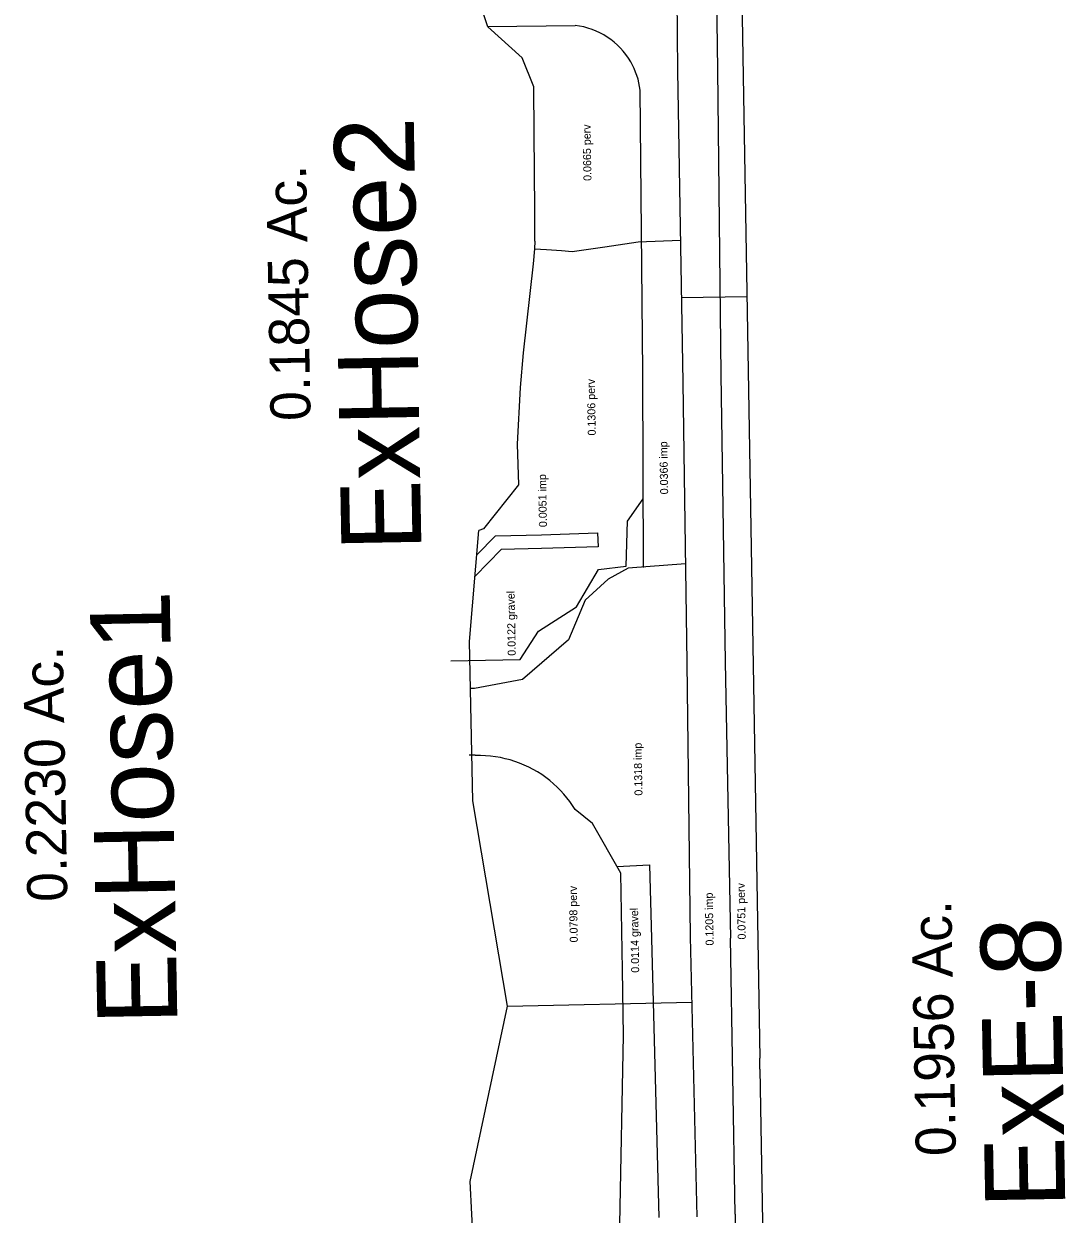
# Model space of a CAD drawing. Extents: x 925564 to 926134, y 853260 to 858402.
# Drawn here: x 925563.8 to 925928.2, y 855967.9 to 856384.4 of the extents above; entities that cross this region are included whole.
import ezdxf

# ---------------------------------------------------------------- set-up
doc = ezdxf.new("R2010")
doc.units = 0
for name, color, linetype in [('DrainDivides01', 7, 'Continuous'), ('PavtMisc_ep', 7, 'Continuous'), ('TextLabel', 7, 'Continuous')]:
    doc.layers.add(name, color=color, linetype=linetype)

msp = doc.modelspace()

# ---------------------------------------------------------------- linework, layer by layer
at = {"layer": 'DrainDivides01'}
for p, q in [((925810.15, 856680.63), (925821.34, 856022.48)), ((925792.29, 856393.71), (925792.52, 856367.9)), ((925792.52, 856367.9), (925794.36, 856258.9)), ((925778.8, 856308.05), (925793.52, 856308.63)), ((925793.86, 856288.6), (925816.81, 856288.99)), ((925794.36, 856258.9), (925795.83, 856160.79)), ((925724.68, 856207.63), (925723.01, 856207.1)), ((925795.83, 856160.79), (925796.98, 856064.9)), ((925796.98, 856064.9), (925799.24, 855966.98)), ((925732.98, 856040.62), (925797.5, 856042.11)), ((925821.38, 856018.6), (925821.34, 856022.48)), ((925821.38, 856018.6), (925832.59, 855359.55))]:
    msp.add_line(p, q, dxfattribs=at)
for points in [[(925726.14, 856383.31), (925722.25, 856395), (925724.71, 856410.17)], [(925742.62, 856308.32), (925742.59, 856313.72), (925742.56, 856319.13), (925742.39, 856346.17), (925742.29, 856362.31), (925738.15, 856372.43), (925726.14, 856383.31)], [(925742.62, 856308.32), (925742.43, 856305.62)], [(925742.43, 856305.62), (925746.63, 856305.37), (925751.95, 856305.05), (925755.65, 856304.67), (925767.07, 856306.34), (925778.8, 856308.05)], [(925742.43, 856305.62), (925742.04, 856300.41), (925738.46, 856269.21), (925737.49, 856257.17), (925736.37, 856237.33), (925736.6, 856230.21), (925736.84, 856223.09), (925724.68, 856207.63)], [(925721.66, 855945.02), (925719.94, 855979.33), (925732.98, 856040.62), (925720.92, 856112.52), (925719.77, 856168.28), (925723.01, 856207.1)], [(925795.31, 856195.44), (925775.3, 856193.89), (925768.29, 856190.12), (925760.26, 856182.68), (925754.4, 856168.86), (925738.25, 856154.97), (925721.53, 856151.86), (925720.11, 856151.83)]]:
    msp.add_lwpolyline(points, dxfattribs=at)
at = {"layer": 'PavtMisc_ep'}
for p, q in [((925806.15, 856396.39), (925806.47, 856368.23)), ((925726.09, 856383.48), (925756.74, 856383.81)), ((925806.47, 856368.23), (925807.73, 856261.68)), ((925780.42, 856262.49), (925779.44, 856361.11)), ((925780.63, 856194.17), (925780.42, 856262.49)), ((925807.73, 856261.68), (925809.17, 856161.07)), ((925744.95, 856205.62), (925764.58, 856206.29)), ((925764.58, 856206.29), (925764.78, 856201.35)), ((925722.3, 856198.61), (925728.86, 856205.27)), ((925728.86, 856205.27), (925744.95, 856205.62)), ((925730.84, 856200.46), (925721.68, 856191.1)), ((925744.95, 856200.83), (925730.84, 856200.46)), ((925764.78, 856201.35), (925744.95, 856200.83)), ((925809.17, 856161.07), (925811.04, 856064.46)), ((925721.77, 856128.5), (925719.61, 856128.46)), ((925721.79, 856128.37), (925721.77, 856128.5)), ((925771.34, 856089.56), (925782.72, 856090.16)), ((925782.72, 856090.16), (925783.38, 856064.34)), ((925783.38, 856064.34), (925786, 855966.7)), ((925812.74, 855967.87), (925811.04, 856064.46))]:
    msp.add_line(p, q, dxfattribs=at)
for points in [[(925713.24, 856161.5), (925737.42, 856161.91), (925743.85, 856171.92), (925757.18, 856180.39), (925764.93, 856193.43), (925774.56, 856194.59), (925775.02, 856210.4), (925780.55, 856218.2)], [(925770.66, 855619.85), (925788.69, 855645.75), (925788.22, 855673.53), (925785.48, 855714.94), (925786.03, 855792.98), (925780.29, 855797.91), (925782.01, 855844.89), (925775.05, 855903.02), (925776.87, 855907.13), (925772.62, 855944.43), (925772.28, 855964.37), (925773.67, 856030.34), (925773.28, 856053.41), (925772.71, 856087.16), (925762.83, 856104.58), (925756.76, 856109.48)]]:
    msp.add_lwpolyline(points, dxfattribs=at)
for centre, major_axis, ratio, start_param, end_param in [((925753.62, 856357.91), (-26.05, -1.75), 0.999394, 3.603265, 4.525427), ((925753.97, 856358.24), (-25.22, -4.62), 0.999489, 3.072825, 3.484768), ((925722.84, 856088.35), (-6.51, 39.5), 0.999783, 5.443851, 6.145934), ((925720.11, 856086.23), (38.92, -19.24), 0.999541, 1.024826, 1.335682), ((925847.43, 855965.66), (3.87, -34.55), 0.999962, 4.537152, 5.134306)]:
    msp.add_ellipse(centre, major_axis=major_axis, ratio=ratio, start_param=start_param, end_param=end_param, dxfattribs=at)

# ---------------------------------------------------------------- texts
at = {"layer": 'TextLabel'}
for s, height, p in [('ExHose2', 28, (925702.93, 856200.07)), ('0.0665 perv', 2.8, (925762.42, 856329.44)), ('0.1845 Ac.', 14, (925664.13, 856245.56)), ('0.1306 perv', 2.8, (925763.93, 856240.35)), ('0.0366 imp', 2.8, (925789.26, 856219.78)), ('0.0051 imp', 2.8, (925746.84, 856208.29)), ('0.0122 gravel', 2.8, (925735.92, 856163.3)), ('ExHose1', 28, (925617.53, 856034.31)), ('0.2230 Ac.', 14, (925579.02, 856077.28)), ('0.1318 imp', 2.8, (925780.28, 856114.35)), ('0.0798 perv', 2.8, (925757.64, 856062.99)), ('0.0751 perv', 2.8, (925816.41, 856063.99)), ('0.1205 imp', 2.8, (925805.18, 856061.89)), ('0.0114 gravel', 2.8, (925779.12, 856052.39)), ('0.1956 Ac.', 14, (925889.93, 855988.32)), ('ExE-8', 28, (925928.24, 855970.19))]:
    msp.add_text(s, height=height, rotation=91.0261, dxfattribs=at).set_placement(p)

doc.saveas('drawing.dxf')
